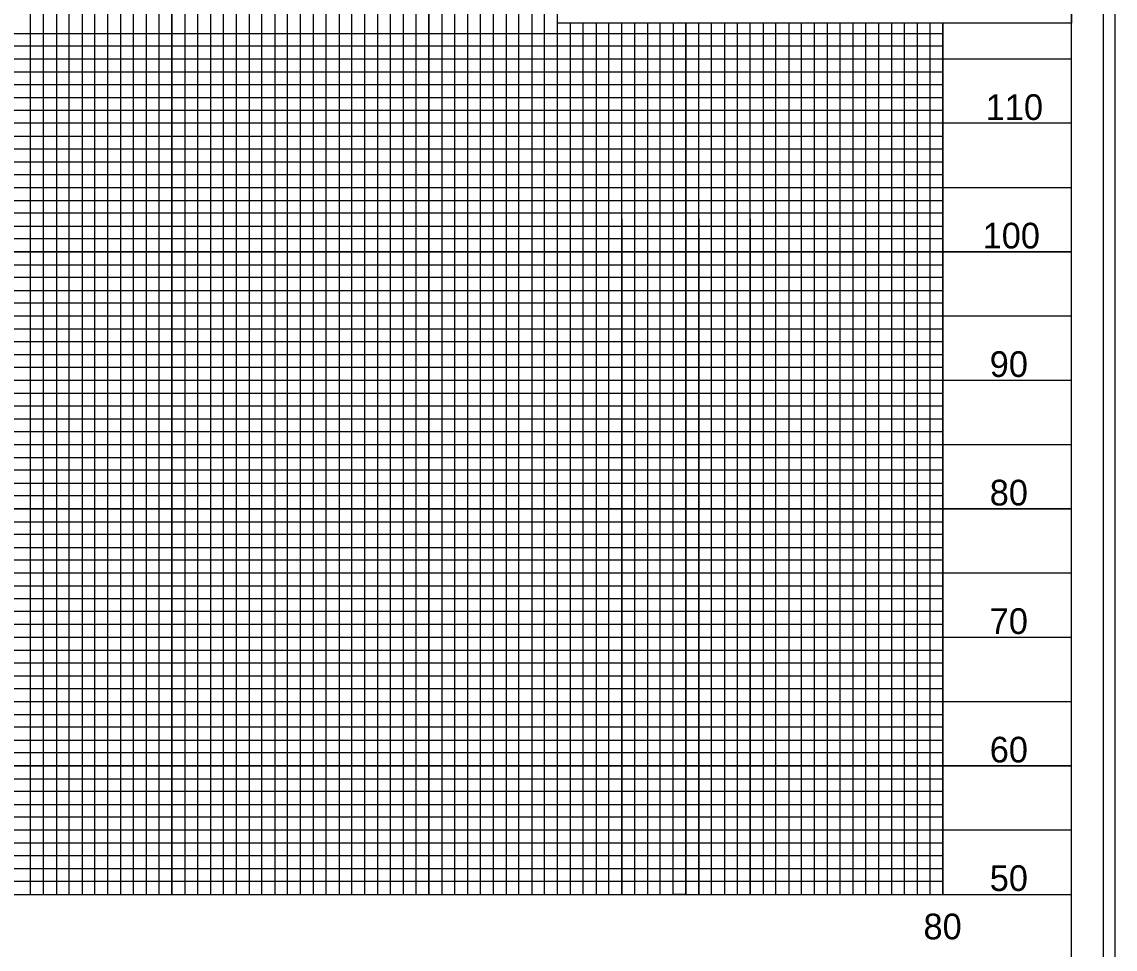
# Model space of a CAD drawing. Extents: x 2367285 to 2374385, y 803279 to 808979.
# Drawn here: x 2373959.6 to 2374385, y 803832.7 to 804193.5 of the extents above; entities that cross this region are included whole.
import ezdxf

# ---------------------------------------------------------------- set-up
doc = ezdxf.new("R2010")
doc.units = 0
for name, color, linetype in [('Old_Level_11', 7, 'Continuous'), ('Old_Level_12', 7, 'Continuous'), ('Old_Level_13', 7, 'Continuous'), ('Old_Level_17', 7, 'Continuous'), ('Old_Level_19', 7, 'Continuous'), ('Old_Level_4', 7, 'Continuous'), ('Old_Level_6', 7, 'Continuous'), ('Old_Level_63', 7, 'Continuous'), ('Old_Level_8', 7, 'Continuous'), ('Old_Level_9', 7, 'Continuous'), ('Plan Sheet CELL', 7, 'Continuous')]:
    doc.layers.add(name, color=color, linetype=linetype)

msp = doc.modelspace()

# ---------------------------------------------------------------- linework, layer by layer
at = {"layer": 'Old_Level_11'}
for points in [[(2373917.97, 803853.98), (2373967.97, 803853.98), (2373967.97, 804353.98), (2374017.97, 804353.98), (2374017.97, 803853.98), (2374067.97, 803853.98), (2374067.97, 804353.98), (2374117.97, 804353.98), (2374117.97, 803853.98), (2374167.97, 803853.98), (2374167.97, 804353.98), (2374194.27, 804353.98)], [(2374317.97, 804192.93), (2374317.97, 803853.98), (2374367.97, 803853.98), (2374367.97, 804203.98)], [(2374217.97, 804192.93), (2374217.97, 803853.98), (2374267.97, 803853.98), (2374267.97, 803853.98), (2374267.97, 804192.93)], [(2374367.97, 804153.98), (2372867.97, 804153.98), (2372867.97, 804103.98), (2374367.97, 804103.98)], [(2374367.97, 804053.98), (2372867.97, 804053.98), (2372867.97, 804003.98), (2374367.97, 804003.98)], [(2374367.97, 803953.98), (2372867.97, 803953.98), (2372867.97, 803953.98), (2372867.97, 803903.98), (2374367.97, 803903.98)]]:
    msp.add_lwpolyline(points, dxfattribs=at)
at = {"layer": 'Old_Level_12'}
for points in [[(2373942.97, 803853.98), (2373992.97, 803853.98), (2373992.97, 804353.98), (2374042.97, 804353.98), (2374042.97, 803853.98), (2374092.97, 803853.98), (2374092.97, 804353.98), (2374142.97, 804353.98), (2374142.97, 803853.98), (2374192.97, 803853.98), (2374192.97, 804192.93)], [(2374192.97, 804116.78), (2374192.97, 803853.98), (2374242.97, 803853.98), (2374242.97, 804192.93)], [(2374242.97, 804116.78), (2374242.97, 803853.98), (2374292.97, 803853.98), (2374292.97, 804192.93)], [(2374367.97, 804178.98), (2372867.97, 804178.98), (2372867.97, 804128.98), (2374192.97, 804128.98)], [(2374192.97, 804128.98), (2374367.97, 804128.98)], [(2374367.97, 804078.98), (2372867.97, 804078.98), (2372867.97, 804028.98), (2374367.97, 804028.98)], [(2374367.97, 803978.98), (2372867.97, 803978.98), (2372867.97, 803928.98), (2374367.97, 803928.98)], [(2374367.97, 803878.98), (2372867.97, 803878.98)]]:
    msp.add_lwpolyline(points, dxfattribs=at)
at = {"layer": 'Old_Level_13'}
for p, q in [((2373967.97, 803853.98), (2373967.97, 804353.98)), ((2374017.97, 803853.98), (2374017.97, 804353.98)), ((2374067.97, 803853.98), (2374067.97, 804353.98)), ((2374117.97, 803853.98), (2374117.97, 804353.98)), ((2374167.97, 803853.98), (2374167.97, 804216.43)), ((2374217.97, 803853.98), (2374217.97, 804192.93)), ((2374267.97, 803853.98), (2374267.97, 804192.93)), ((2374317.97, 803853.98), (2374317.97, 804192.93)), ((2374367.97, 804153.98), (2372867.97, 804153.98)), ((2374367.97, 804103.98), (2372867.97, 804103.98)), ((2374367.97, 804053.98), (2372867.97, 804053.98)), ((2374367.97, 804003.98), (2372867.97, 804003.98)), ((2374367.97, 803953.98), (2372867.97, 803953.98)), ((2374367.97, 803903.98), (2372867.97, 803903.98))]:
    msp.add_line(p, q, dxfattribs=at)
at = {"layer": 'Old_Level_4'}
msp.add_lwpolyline([(2372713.97, 803301.43), (2374380.47, 803301.43), (2374380.47, 804356.53), (2372713.97, 804356.53)], close=True, dxfattribs=at)
at = {"layer": 'Old_Level_6'}
msp.add_lwpolyline([(2372700.97, 803278.98), (2374384.97, 803278.98), (2374384.97, 804378.98), (2372700.97, 804378.98)], close=True, dxfattribs=at)
at = {"layer": 'Old_Level_63'}
msp.add_lwpolyline([(2372917.97, 804192.93), (2372917.97, 803853.98), (2374317.97, 803853.98), (2374317.97, 804192.93)], dxfattribs=at)
at = {"layer": 'Old_Level_8'}
for p, q in [((2372917.97, 804188.98), (2374317.97, 804188.98)), ((2374317.97, 804168.98), (2372917.97, 804168.98)), ((2372917.97, 804163.98), (2374317.97, 804163.98)), ((2374317.97, 804143.98), (2372917.97, 804143.98)), ((2372917.97, 804138.98), (2374317.97, 804138.98)), ((2374317.97, 804118.98), (2372917.97, 804118.98)), ((2372917.97, 804113.98), (2374317.97, 804113.98)), ((2374317.97, 804108.98), (2372917.97, 804108.98)), ((2372917.97, 804098.98), (2374317.97, 804098.98)), ((2374317.97, 804093.98), (2372917.97, 804093.98)), ((2372917.97, 804088.98), (2374317.97, 804088.98)), ((2374317.97, 804083.98), (2372917.97, 804083.98)), ((2372917.97, 804073.98), (2374317.97, 804073.98)), ((2374317.97, 804068.98), (2372917.97, 804068.98)), ((2372917.97, 804063.98), (2374317.97, 804063.98)), ((2374317.97, 804058.98), (2372917.97, 804058.98)), ((2372917.97, 804048.98), (2374317.97, 804048.98)), ((2374317.97, 804043.98), (2372917.97, 804043.98)), ((2372917.97, 804038.98), (2374317.97, 804038.98)), ((2374317.97, 804033.98), (2372917.97, 804033.98)), ((2372917.97, 804023.98), (2374317.97, 804023.98)), ((2374317.97, 804018.98), (2372917.97, 804018.98)), ((2372917.97, 804013.98), (2374317.97, 804013.98)), ((2374317.97, 804008.98), (2372917.97, 804008.98)), ((2372917.97, 803998.98), (2374317.97, 803998.98)), ((2374317.97, 803993.98), (2372917.97, 803993.98)), ((2372917.97, 803988.98), (2374317.97, 803988.98)), ((2374317.97, 803983.98), (2372917.97, 803983.98)), ((2372917.97, 803973.98), (2374317.97, 803973.98)), ((2374317.97, 803968.98), (2372917.97, 803968.98)), ((2374317.97, 803963.98), (2372917.97, 803963.98)), ((2374317.97, 803958.98), (2372917.97, 803958.98)), ((2372917.97, 803948.98), (2374317.97, 803948.98)), ((2374317.97, 803943.98), (2372917.97, 803943.98)), ((2372917.97, 803938.98), (2374317.97, 803938.98)), ((2374317.97, 803933.98), (2372917.97, 803933.98)), ((2372917.97, 803923.98), (2374317.97, 803923.98)), ((2374317.97, 803918.98), (2372917.97, 803918.98)), ((2372917.97, 803913.98), (2374317.97, 803913.98)), ((2374317.97, 803908.98), (2372917.97, 803908.98)), ((2372917.97, 803898.98), (2374317.97, 803898.98)), ((2374317.97, 803893.98), (2372917.97, 803893.98)), ((2372917.97, 803888.98), (2374317.97, 803888.98)), ((2374317.97, 803883.98), (2372917.97, 803883.98)), ((2372917.97, 803873.98), (2374317.97, 803873.98)), ((2374317.97, 803868.98), (2372917.97, 803868.98)), ((2372917.97, 803863.98), (2374317.97, 803863.98))]:
    msp.add_line(p, q, dxfattribs=at)
for points in [[(2373957.97, 803853.98), (2373962.97, 803853.98), (2373962.97, 804353.98)], [(2373972.97, 804353.98), (2373972.97, 803853.98), (2373977.97, 803853.98), (2373977.97, 804353.98)], [(2373982.97, 804353.98), (2373982.97, 803853.98), (2373987.97, 803853.98), (2373987.97, 804353.98)], [(2373997.97, 804353.98), (2373997.97, 803853.98), (2374002.97, 803853.98), (2374002.97, 804353.98)], [(2374007.97, 804353.98), (2374007.97, 803853.98), (2374012.97, 803853.98), (2374012.97, 804353.98)], [(2374022.97, 804353.98), (2374022.97, 803853.98), (2374027.97, 803853.98), (2374027.97, 804353.98)], [(2374032.97, 804353.98), (2374032.97, 803853.98), (2374037.97, 803853.98), (2374037.97, 804353.98)], [(2374047.97, 804353.98), (2374047.97, 803853.98), (2374052.97, 803853.98), (2374052.97, 804353.98)], [(2374057.97, 804353.98), (2374057.97, 803853.98)], [(2374057.97, 803853.98), (2374062.97, 803853.98), (2374062.97, 804353.98)], [(2374072.97, 804353.98), (2374072.97, 803853.98), (2374077.97, 803853.98), (2374077.97, 804353.98)], [(2374082.97, 804353.98), (2374082.97, 803853.98), (2374087.97, 803853.98), (2374087.97, 804353.98)], [(2374097.97, 804353.98), (2374097.97, 803853.98), (2374102.97, 803853.98), (2374102.97, 804353.98)], [(2374107.97, 804353.98), (2374107.97, 803853.98), (2374112.97, 803853.98), (2374112.97, 804353.98)], [(2374122.97, 804353.98), (2374122.97, 803853.98), (2374127.97, 803853.98), (2374127.97, 804353.98)], [(2374132.97, 804353.98), (2374132.97, 803853.98), (2374137.97, 803853.98), (2374137.97, 804353.98)], [(2374147.97, 804353.98), (2374147.97, 803853.98), (2374152.97, 803853.98), (2374152.97, 804353.98)], [(2374157.97, 804353.98), (2374157.97, 803853.98), (2374162.97, 803853.98), (2374162.97, 804353.98)], [(2374172.97, 804192.93), (2374172.97, 803853.98), (2374177.97, 803853.98), (2374177.97, 804192.93)], [(2374182.97, 804192.93), (2374182.97, 803853.98), (2374187.97, 803853.98), (2374187.97, 804192.93)], [(2374197.97, 804192.93), (2374197.97, 803853.98), (2374197.97, 803853.98), (2374202.97, 803853.98), (2374207.97, 803853.98), (2374207.97, 804192.93)], [(2374202.97, 804192.93), (2374202.97, 803853.98)], [(2374212.97, 804192.93), (2374212.87, 803854.03), (2374217.87, 803854.03), (2374222.97, 803853.98), (2374222.97, 804192.93)], [(2374222.97, 804116.78), (2374222.97, 803853.98), (2374227.97, 803853.98), (2374227.97, 804192.93)], [(2374232.97, 804192.93), (2374232.97, 803853.98), (2374237.97, 803853.98), (2374237.97, 804192.93)], [(2374247.97, 804192.93), (2374247.97, 803853.98), (2374252.97, 803853.98), (2374252.97, 804192.93)], [(2374257.97, 804192.93), (2374257.97, 803853.98), (2374262.97, 803853.98), (2374262.97, 804192.93)], [(2374272.97, 804192.93), (2374272.97, 803853.98), (2374277.97, 803853.98), (2374277.97, 804192.93)], [(2374282.97, 804192.93), (2374282.97, 803853.98), (2374287.97, 803853.98), (2374287.97, 804192.93)], [(2374297.97, 804192.93), (2374297.97, 803853.98), (2374302.97, 803853.98), (2374302.97, 804192.93)], [(2374307.97, 804192.93), (2374307.97, 803853.98), (2374312.97, 803853.98), (2374312.97, 804192.93)], [(2374317.97, 804183.98), (2372917.97, 804183.98), (2372917.97, 804173.98), (2374317.97, 804173.98)], [(2374317.97, 804158.98), (2372917.97, 804158.98), (2372917.97, 804148.98), (2374317.97, 804148.98)], [(2374317.97, 804133.98), (2372917.97, 804133.98), (2372917.97, 804123.98), (2374317.97, 804123.98)], [(2374317.97, 803858.98), (2372917.97, 803858.98)]]:
    msp.add_lwpolyline(points, dxfattribs=at)
at = {"layer": 'Old_Level_9'}
msp.add_line((2372867.97, 803853.98), (2374367.97, 803853.98), dxfattribs=at)
msp.add_lwpolyline([(2374367.97, 804353.98), (2372867.97, 804353.98), (2372867.97, 803303.98), (2374367.97, 803303.98)], close=True, dxfattribs=at)
at = {"layer": 'Plan Sheet CELL'}
for p, q in [((2374167.92, 804192.93), (2374167.92, 804216.43)), ((2374167.92, 804192.93), (2374167.92, 804216.43)), ((2374367.96, 804216.42), (2374367.96, 804192.92)), ((2374367.96, 804216.42), (2374367.96, 804192.92)), ((2374367.96, 804192.93), (2374167.92, 804192.93)), ((2374367.96, 804192.93), (2374167.92, 804192.93))]:
    msp.add_line(p, q, dxfattribs=at)

# ---------------------------------------------------------------- texts
at = {"layer": 'Old_Level_17'}
for s, p in [('110', (2374334.61, 804155.29)), ('110', (2374334.61, 804155.29)), ('100', (2374333.41, 804105.29)), ('100', (2374333.41, 804105.29)), ('90', (2374336.17, 804055.29)), ('90', (2374336.17, 804055.29)), ('80', (2374336.17, 804005.29)), ('80', (2374336.17, 804005.29)), ('70', (2374336.17, 803955.29)), ('70', (2374336.17, 803955.29)), ('60', (2374336.17, 803905.29)), ('60', (2374336.17, 803905.29)), ('50', (2374336.17, 803855.29)), ('50', (2374336.17, 803855.29))]:
    msp.add_text(s, height=10, dxfattribs=at).set_placement(p)
at = {"layer": 'Old_Level_19'}
msp.add_text('80', height=10, dxfattribs=at).set_placement((2374310.4, 803836.48))

doc.saveas('drawing.dxf')
